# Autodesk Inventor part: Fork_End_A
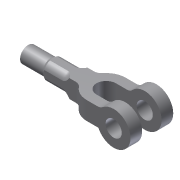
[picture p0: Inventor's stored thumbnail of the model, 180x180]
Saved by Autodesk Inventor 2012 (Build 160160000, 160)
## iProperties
Created: 2011-09
Part Number: Fork_End_A
Material: Default
Document SubType Name: Modeling
Designer: CADCIM
Density: 1 g/cm^3
Author: CADCIM
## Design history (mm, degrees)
sketch "Sketch1"
  geometry: 1 further point
sketch "Sketch2"
  geometry: L1 (0, 0)-(129, 0); L2 (130, 14)-(27.713, 14); L3 (27.713, -14)-(130, -14); L4 (130, 14)-(130, -14); C1 r 12.5 at (0, 0); A1 r 26 centre (0, 0) between (18.961, 17.789) and (18.961, -17.789); A2 r 12 centre (27.713, 26) between (18.961, 17.789) and (27.713, 14); A3 r 12 centre (27.713, -26) between (27.713, -14) and (18.961, -17.789); 3 further points
  constraints: 8 end point, 8 point on circle, 4 centre point, 4 tangent, 2 coincident, 2 parallel, 2 point on line, 1 equal radius, 1 horizontal, 1 perpendicular, 1 other
  dimensions: "d0" = 25 diameter of C1; "d1" = 52 diameter of A1; "d2" = 28 distance between parallel lines of L3 L2; "d3" = 12 radius of A2; "d4" = 130 distance from line of L4 point (0, 0)
extrude "Extrusion1" new body sketch "Sketch2" stored distance "d5" = 60; taper "d6" = 0 deg
sketch "Sketch3"
  geometry: C1 r 12.5 at (0, 0) reference; C2 r 12.5 at (0, 0); C3 r 26 at (0, 0); A1 r 26 centre (0, 0) between (-18.961, -17.789) and (-18.961, 17.789) reference
  constraints: 2 centre point, 2 coincident, 2 concentric
extrude "Extrusion2" join sketch "Sketch3" distance "d7" = 3; taper "d8" = 0 deg
mirror "Mirror1"
sketch "Sketch4"
  geometry: L1 (27.5, 15)-(-44.5, 15); L2 (-44.5, -15)-(27.5, -15); L3 (27.5, -15)-(27.5, 15); L4 (0, 0)-(-140, 0); A1 r 15 centre (-44.5, 0) between (-44.5, 15) and (-44.5, -15)
  constraints: 8 end point, 2 point on circle, 2 tangent, 1 centre point, 1 horizontal, 1 parallel, 1 perpendicular, 1 other
  dimensions: "d9" = 15 radius of A1; "d10" = 44.5 distance of L4.start A1.centre; "d11" = 72 distance of L1.start L1.end
extrude "Extrusion3" cut sketch "Sketch4" stored distance "d12" = 85.25; taper "d13" = 0 deg
sketch "Sketch5"
  geometry: L1 (0, 0)-(-145, 0); L2 (-130, 14)-(-71.033, 14); L3 (-130, -30)-(-130, 30) reference; L4 (-130, 14)-(-130, 30); L5 (-130, 30)-(-27.713, 30) reference; L6 (-27.713, -30)-(-130, -30) reference; L7 (-130, 30)-(-44.5, 30); A1 r 15 centre (-44.5, 0) between (-44.5, 15) and (-44.5, -15) reference; A2 r 30 centre (-44.5, 0) between (-44.5, 30) and (-71.033, 14)
  constraints: 8 end point, 2 point on circle, 1 centre point, 1 coincident, 1 collinear, 1 horizontal, 1 point on line
  dimensions: "d17" = 30 radius of A2; "d18" = 28 diameter of L2 L1
extrude "Extrusion4" cut sketch "Sketch5" stored distance "d19" = 1; taper "d20" = 0 deg
mirror "Mirror2"
sketch "Sketch6"
  geometry: C1 r 12.5 at (14, -14); 1 further point
  constraints: 1 centre point, 1 coincident
  dimensions: "d21" = 25 diameter of C1
extrude "Extrusion5" join sketch "Sketch6" distance "d22" = 35; taper "d23" = 0 deg
sketch "Sketch8"
  geometry: L1 (130, 14)-(71.033, 14) reference; L2 (130, -14)-(130, 14) reference; L3 (130, 15)-(97.799, 15); L4 (87.899, 19.101)-(86, 21); L5 (86, 21)-(130, 21); L6 (130, 21)-(130, 15); L7 (0, 0)-(183, 0); A1 r 14 centre (97.799, 29) between (87.899, 19.101) and (97.799, 15)
  constraints: 10 end point, 3 perpendicular, 2 point on circle, 2 tangent, 1 centre point, 1 collinear, 1 parallel
  dimensions: "d33" = 135 deg angle of L3 L4; "d34" = 14 radius of A1; "d35" = 44 distance of L4.end L5.end; "d36" = 6 distance of L5.end L3.start; "d37" = 1 distance between parallel lines of L1 L3
revolve "Revolution3" sketch "Sketch8" stored, may be unused: angle "d38" = 90 deg
sketch "Sketch11"
  geometry: C1 r 12.5 at (-14, 5.385) reference; C2 r 12.5 at (-14, 5.385); C3 r 17.5 at (-14, 5.385); A1 r 15 centre (-14, 5.385) between (-19.385, 19.385) and (-28, 10.77) reference
  constraints: 2 centre point, 2 concentric, 1 coincident
  dimensions: "d46" = 35 diameter of C3
extrude "Extrusion8" cut sketch "Sketch11" distance "d44" = 5; taper "d45" = -32 deg
fillet "Fillet1" dims "d47" = 12
body "Solid1"
